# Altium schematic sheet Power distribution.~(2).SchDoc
size A3; SheetNumber: 7; SheetTotal: 8
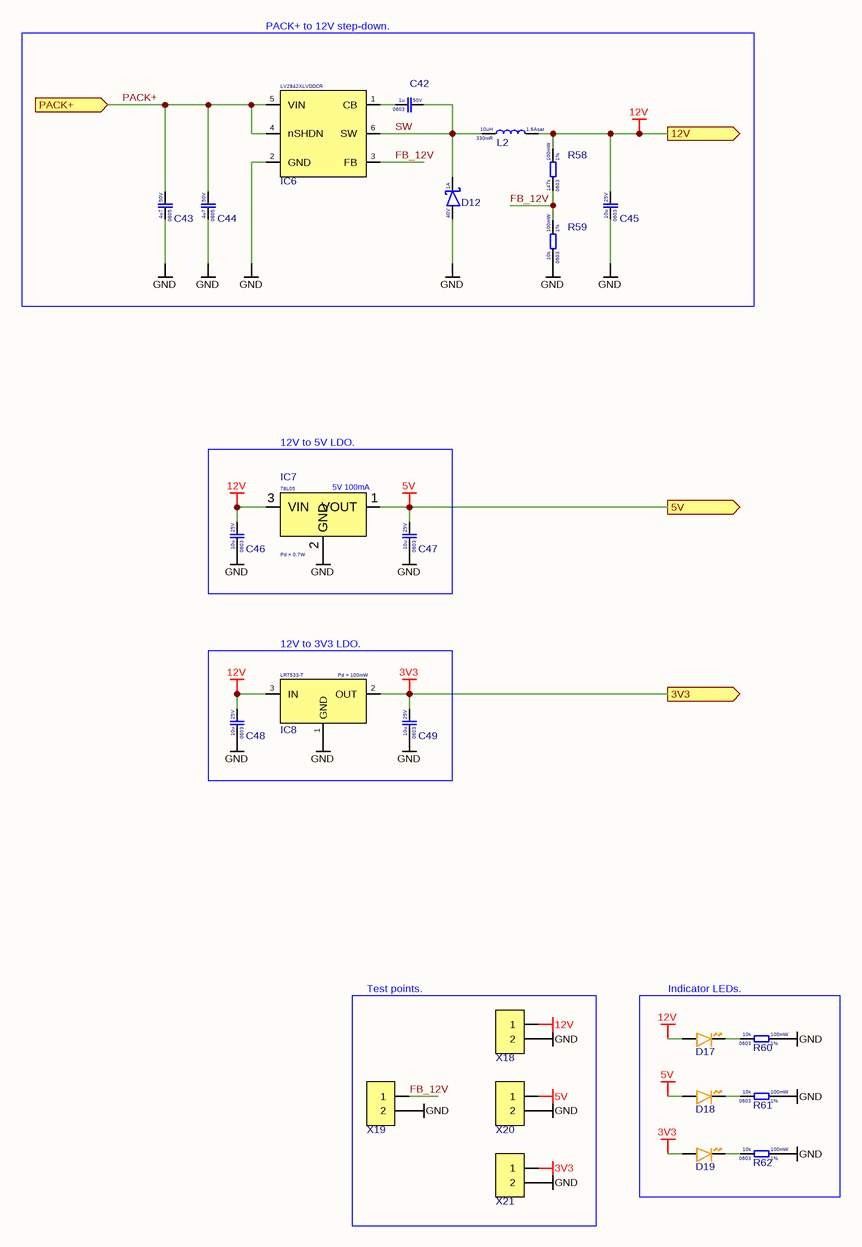
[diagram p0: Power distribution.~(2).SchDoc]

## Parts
C42  Voltage Rating: 50V  Case Code (Imperial): 0603  Capacitance: 1u  [CAP 0603]  (hidden comment: CL10A105KB8NNNC)
C43  Voltage Rating: 50V  Case Code (Imperial): 0805  Capacitance: 4u7  [Cap_0805]  (hidden comment: CL21A475KBQNNNE)
C44  Voltage Rating: 50V  Case Code (Imperial): 0805  Capacitance: 4u7  [Cap_0805]  (hidden comment: CL21A475KBQNNNE)
C45  Voltage Rating: 25V  Case Code (Imperial): 0603  Capacitance: 10u  [CAP 0603]  (hidden comment: CL10A106MA8NRNC)
C46  Voltage Rating: 25V  Case Code (Imperial): 0603  Capacitance: 10u  [CAP 0603]  (hidden comment: CL10A106MA8NRNC)
C47  Voltage Rating: 25V  Case Code (Imperial): 0603  Capacitance: 10u  [CAP 0603]  (hidden comment: CL10A106MA8NRNC)
C48  Voltage Rating: 25V  Case Code (Imperial): 0603  Capacitance: 10u  [CAP 0603]  (hidden comment: CL10A106MA8NRNC)
C49  Voltage Rating: 25V  Case Code (Imperial): 0603  Capacitance: 10u  [CAP 0603]  (hidden comment: CL10A106MA8NRNC)
D12  Forward Current: 1A  Reverse Voltage: 40V  [SOD-323]  (hidden comment: 1N5819WS)
D17  XL-1608UOC-06  [DIODE_0603_ORANGE]  (value not drawn)
D18  XL-1608UOC-06  [DIODE_0603_ORANGE]  (value not drawn)
D19  XL-1608UOC-06  [DIODE_0603_ORANGE]  (value not drawn)
IC6  LV2842XLVDDCR  [SOT-23-6]
IC7  Pd = 0.7W  [SOT-89-3]
IC8  Pd = 100mW  [SOT-23 123]
L2  Resistance: 330mR  Saturation current: 1.6Asat  Inductance: 10uH  [IND 1008]  (hidden comment: FTC252012S100MBCA)
R58  Resistance Tolerance: 1%  Resistance: 147k  Power Rating: 100mW  Case Code (Imperial): 0603  [RES_0603]  (hidden comment: 0603WAF1473T5E)
R59  Resistance Tolerance: 1%  Resistance: 10k  Power Rating: 100mW  Case Code (Imperial): 0603  [RES_0603]  (hidden comment: 0603WAF1002T5E)
R60  Resistance Tolerance: 1%  Resistance: 10k  Power Rating: 100mW  Case Code (Imperial): 0603  [RES_0603]  (hidden comment: 0603WAF1002T5E)
R61  Resistance Tolerance: 1%  Resistance: 10k  Power Rating: 100mW  Case Code (Imperial): 0603  [RES_0603]  (hidden comment: 0603WAF1002T5E)
R62  Resistance Tolerance: 1%  Resistance: 10k  Power Rating: 100mW  Case Code (Imperial): 0603  [RES_0603]  (hidden comment: 0603WAF1002T5E)
X18  ZX-PZ1.27-1-2PZZ  [Pin header 1x2 1.27mmP THT Vertical]  (value not drawn)
X19  ZX-PZ1.27-1-2PZZ  [Pin header 1x2 1.27mmP THT Vertical]  (value not drawn)
X20  ZX-PZ1.27-1-2PZZ  [Pin header 1x2 1.27mmP THT Vertical]  (value not drawn)
X21  ZX-PZ1.27-1-2PZZ  [Pin header 1x2 1.27mmP THT Vertical]  (value not drawn)

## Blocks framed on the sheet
PACK+ to 12V step-down.: C42-C45 D12 IC6 L2 R58 R59
12V to 5V LDO.: C46 C47 IC7
12V to 3V3 LDO.: C48 C49 IC8
Test points.: X18-X21
Indicator LEDs.: D17-D19 R60-R62

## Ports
3V3 (out, see CHARGER[4C], USB PD[5B]), 5V (out, see CHARGER[4C], USB PD[2B]), 12V (out, see CHARGER[4C], Charger BQ25756[8A]), PACK+ (in, see CHARGER[3C], BMS[8A], Charger BQ25756[1A], CHARGER[1B])

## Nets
3V3: C49.2 D19.A IC8.2(OUT) X21.1 ; port 3V3
5V: C47.2 D18.A IC7.1(VOUT) X20.1 ; port 5V
12V: C45.2 C46.2 C48.2 D17.A IC7.3(VIN) IC8.3(IN) L2.2 R58.2 X18.1 ; port 12V
GND: C43.1 C44.1 C45.1 C46.1 C47.1 C48.1 C49.1 D12.A IC6.2(GND) IC7.2(GND) IC8.1(GND) R59.1 R60.2 R61.2 R62.2 X18.2 X19.2 X20.2 X21.2
FB_12V: IC6.3(FB) R58.1 R59.2 X19.1
PACK+: C43.2 C44.2 IC6.4(nSHDN) IC6.5(VIN) ; port PACK+
SW: C42.2 D12.K IC6.6(SW) L2.1
NetC42_1: C42.1 IC6.1(CB)
NetD17_K: D17.K R60.1
NetD18_K: D18.K R61.1
NetD19_K: D19.K R62.1

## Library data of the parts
C42 = CL10A105KB8NNNC: Cap 1uF 50V 0603 X5R; Manufacturer: Samsung
C43 C44 = CL21A475KBQNNNE: Cap 4.7uF 50V 0805 X5R; Manufacturer: Samsung
C45-C49 = CL10A106MA8NRNC: Cap 10uF 25V 0603 X5R; Manufacturer: Samsung
D12 = 1N5819WS: Schottky 40V 1A 600mVf SOD-323; Manufacturer: Guangdong Hottech
D17-D19 = XL-1608UOC-06: LED Orange 0603 20mA; Manufacturer: XINGLIGHT
IC6 = LV2842XLVDDCR: Step-down converter 4~40Vin 600mAout Adjustible SOT23-6; Manufacturer: Texas Instruments
IC7 = 78L05: LDO 5V 100mA 30Vin; Manufacturer: UMW
IC8 = LR7533-T: LDO 24Vin 3.3Vout fixed; Manufacturer: LR
L2 = FTC252012S100MBCA: Inductor 10uH 1.6Asat 330mR; Manufacturer: cjiang
R58 = 0603WAF1473T5E: Res 147k 0603 1% 100mW 75V; Manufacturer: Uni-Royal
R59-R62 = 0603WAF1002T5E: Res 10k 0603 1% 100mW 75V; Manufacturer: Uni-Royal
X18-X21 = ZX-PZ1.27-1-2PZZ: Pin header 1x2 1.27mmP THT Vertical; Manufacturer: Megastar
